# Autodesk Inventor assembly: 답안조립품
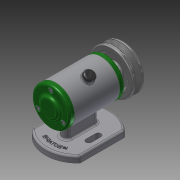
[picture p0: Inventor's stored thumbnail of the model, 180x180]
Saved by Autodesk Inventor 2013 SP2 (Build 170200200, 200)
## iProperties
Created: 2022-02
Part Number: 답안조립품
Document SubType Name: Assembly
Designer: a
Author: a
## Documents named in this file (14)
- C:\Users\a\Desktop\720206V1019\답안조립품.iam
- C:\Users\a\Desktop\720206V1019\본체.ipt
- C:\Users\a\Desktop\720206V1019\V벨트풀리.ipt
- C:\Users\a\Desktop\720206V1019\고무 캡.ipt
- C:\Users\a\Desktop\720206V1019\너트 M8.ipt
- C:\Users\a\Desktop\720206V1019\뒤커버.ipt
- C:\Users\a\Desktop\720206V1019\베어링 6002.ipt
- C:\Users\a\Desktop\720206V1019\볼트 M4 x 10.ipt
- C:\Users\a\Desktop\720206V1019\스프링와셔 8.ipt
- C:\Users\a\Desktop\720206V1019\앞커버.ipt
- C:\Users\a\Desktop\720206V1019\오일 실 15 x 25 x 7.ipt
- C:\Users\a\Desktop\720206V1019\축.ipt
- C:\Users\a\Desktop\720206V1019\키 3 x 3 x 12.ipt
- C:\Users\a\Desktop\720206V1019\평와셔 8 x 17.ipt
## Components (2 placed, 2 different names)
1. V벨트풀리:1
2. 고무 캡:1
